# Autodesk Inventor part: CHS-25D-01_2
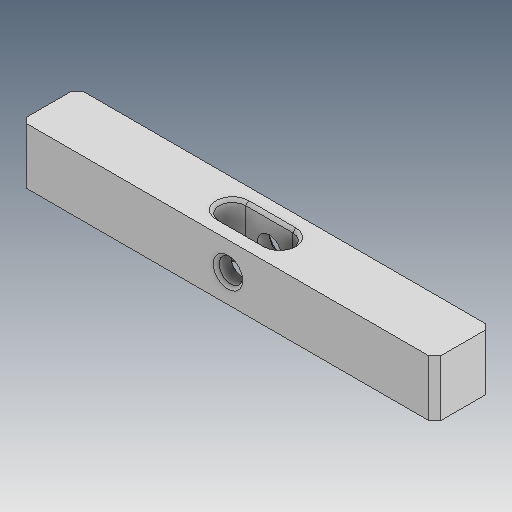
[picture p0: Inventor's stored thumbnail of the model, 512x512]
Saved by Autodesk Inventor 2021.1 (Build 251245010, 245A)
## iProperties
Created: 2019-04
Part Number: CHS-25D-01_2
Material: Ogólny
Document SubType Name: Modeling
Designer: user
Density: 1 g/cm^3
Appearance: Domyślna
Author: user
Revision Number: ÈÎºÎ
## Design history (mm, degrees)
feature "ÊäÈë1"
node "Bryła1"
